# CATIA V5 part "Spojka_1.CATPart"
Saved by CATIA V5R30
Part number: Spojka_1
Definition: E 2000_9_14_1
Nomenclature: E 2000_9_14_1
Source: Unknown
Description: PART-E 2000_9_14_1-DESC
Bounding box of the stored display mesh (mm): x -8.66 to 8.66, y -7.5 to 7.5, z -9 to 17
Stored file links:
  E:\Bakalarka\Model\Forma_v7\Spojka_1.CATPart
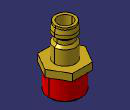
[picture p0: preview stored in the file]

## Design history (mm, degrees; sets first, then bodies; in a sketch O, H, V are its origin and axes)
Body1 "E 2000_9_14" (main body)
  Solid1: solid without history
